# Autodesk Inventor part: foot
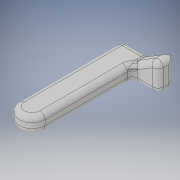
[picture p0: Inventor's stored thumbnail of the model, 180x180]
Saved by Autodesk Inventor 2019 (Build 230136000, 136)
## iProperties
Created: 2020-09
Part Number: foot
Material: 一般
Document SubType Name: Modeling
Designer: kikut
Density: 1 g/cm^3
Appearance: 既定
Author: kikut
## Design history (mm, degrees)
sketch "スケッチ1"
  geometry: L1 (-0.005, -0.08)-(0.005, -0.08); L2 (0.005, -0.08)-(0.005, -0.04); L3 (0.005, -0.04)-(-0.005, -0.04); L4 (-0.005, -0.04)-(-0.005, -0.08); L5 (-0.005, -0.08)-(0.005, -0.04); L6 (0.005, -0.08)-(-0.005, -0.04); L7 (0, -0.096)-(0, 0.016) reference; A1 r 0.005 centre (0, -0.04) between (0.005, -0.04) and (-0.005, -0.04); 2 further points
  constraints: 12 end point, 4 midpoint, 2 parallel, 2 point on circle, 1 centre point, 1 horizontal, 1 perpendicular, 1 other
  dimensions: "d0" = 0.04 distance of L1.end L2.end; "d1" = 0.04 distance from line of L3 point (0, 0); "d2" = 0.01 distance of L2.end L3.end
extrude "押し出し1" new body sketch "スケッチ1" stored distance "d3" = 0.006; taper "d4" = 0 deg
sketch "スケッチ2"
  geometry: L1 (0, -0.006)-(0.01, -0.006) reference; L2 (0, -0.006)-(-0.01, -0.006); L3 (-0.01, -0.006)-(-0.01, 0.006); L4 (-0.01, 0.006)-(0, 0); L5 (0, 0)-(0, -0.006); 1 further point
  constraints: 8 end point, 1 horizontal, 1 parallel, 1 perpendicular
  dimensions: "d5" = 0.01 distance of L1.start L2.end; "d6" = 0.012 distance of L2.end L3.end
extrude "押し出し2" join sketch "スケッチ2" distance "d7" = 0.006; taper "d8" = 0 deg
fillet "フィレット1" dims "d9" = 0.002
node "ソリッド1"
